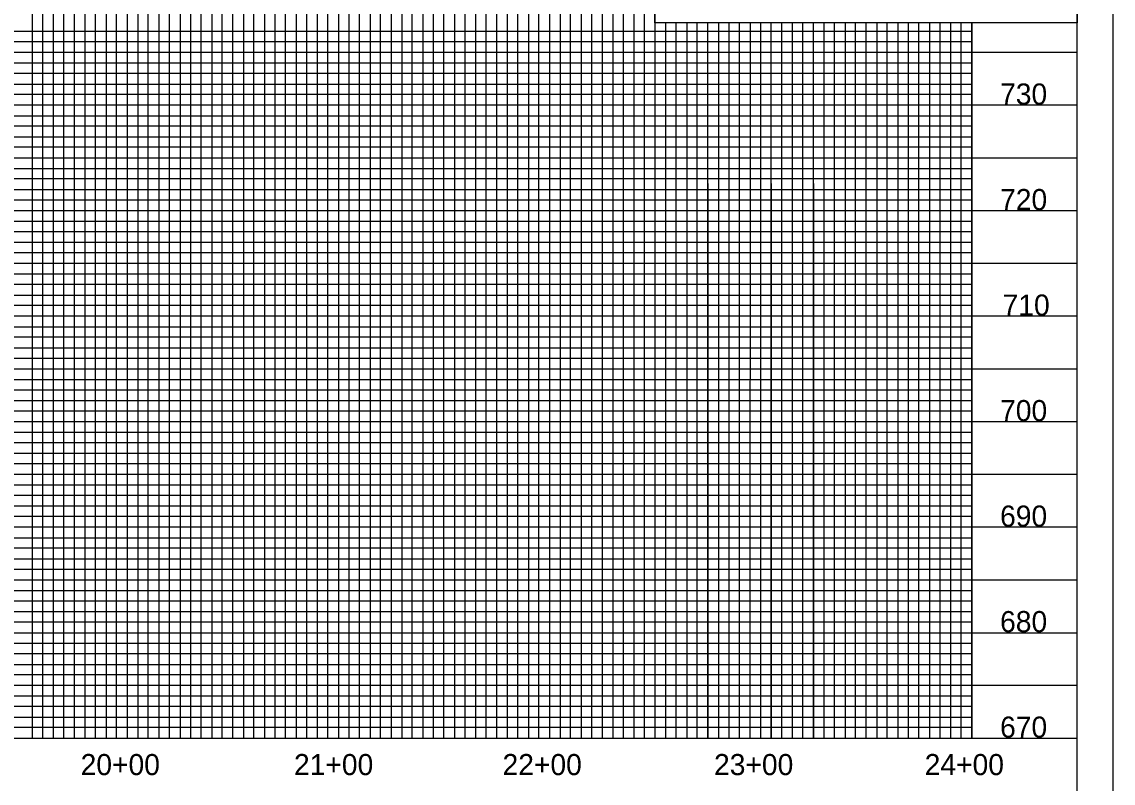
# Model space of a CAD drawing. Extents: x 1524869 to 1526553, y 501099 to 502199.
# Drawn here: x 1526036 to 1526553, y 501652 to 502013 of the extents above; entities that cross this region are included whole.
import ezdxf

# ---------------------------------------------------------------- set-up
doc = ezdxf.new("R2010")
doc.units = 0
for name, color, linetype in [('Exist Vertical Profile Horizontal Axis Label Major', 7, 'Continuous'), ('Exist Vertical Profile Vertical Axis Label', 7, 'Continuous'), ('Sheet Layout Profile Border Port 1', 7, 'Continuous'), ('Sheet Plot Border Outside CELL', 7, 'Continuous'), ('Sheet Profile CELL', 7, 'Continuous'), ('Sheet Profile Grid Major CELL', 7, 'Continuous'), ('Sheet Profile Grid Middle CELL', 7, 'Continuous'), ('Sheet Profile Grid Minor CELL', 7, 'Continuous'), ('Sheet Sticker Exception Certification CELL', 7, 'Continuous')]:
    doc.layers.add(name, color=color, linetype=linetype)

msp = doc.modelspace()

# ---------------------------------------------------------------- linework, layer by layer
at = {"layer": 'Sheet Layout Profile Border Port 1'}
msp.add_lwpolyline([(1525086.08, 502173.56), (1525086.08, 501673.56), (1526486.08, 501673.56), (1526486.08, 502012.51), (1526336.03, 502012.51), (1526336.08, 502173.56)], close=True, dxfattribs=at)
at = {"layer": 'Sheet Plot Border Outside CELL'}
msp.add_lwpolyline([(1524869.08, 501098.56), (1526553.08, 501098.56), (1526553.08, 502198.56), (1524869.08, 502198.56)], close=True, dxfattribs=at)
at = {"layer": 'Sheet Profile CELL'}
msp.add_line((1525036.08, 501673.56), (1526536.08, 501673.56), dxfattribs=at)
msp.add_lwpolyline([(1526536.08, 502173.56), (1525036.08, 502173.56), (1525036.08, 501123.56), (1526536.08, 501123.56)], close=True, dxfattribs=at)
at = {"layer": 'Sheet Profile Grid Major CELL'}
for points in [[(1526036.08, 502173.56), (1526086.08, 502173.56), (1526086.08, 501673.56), (1526136.08, 501673.56), (1526136.08, 502173.56), (1526186.08, 502173.56), (1526186.08, 501673.56), (1526236.08, 501673.56), (1526236.08, 502173.56), (1526286.08, 502173.56), (1526286.08, 501673.56), (1526336.08, 501673.56), (1526336.08, 502173.56), (1526362.38, 502173.56)], [(1526486.08, 502012.51), (1526486.08, 501673.56), (1526536.08, 501673.56), (1526536.08, 502023.56)], [(1526386.08, 502012.51), (1526386.08, 501673.56), (1526436.08, 501673.56), (1526436.08, 501673.56), (1526436.08, 502012.51)], [(1526536.08, 501973.56), (1525036.08, 501973.56), (1525036.08, 501923.56), (1526536.08, 501923.56)], [(1526536.08, 501873.56), (1525036.08, 501873.56), (1525036.08, 501823.56), (1526536.08, 501823.56)], [(1526536.08, 501773.56), (1525036.08, 501773.56), (1525036.08, 501773.56), (1525036.08, 501723.56), (1526536.08, 501723.56)]]:
    msp.add_lwpolyline(points, dxfattribs=at)
at = {"layer": 'Sheet Profile Grid Middle CELL'}
for points in [[(1526011.08, 501673.56), (1526061.08, 501673.56), (1526061.08, 502173.56), (1526111.08, 502173.56), (1526111.08, 501673.56), (1526161.08, 501673.56), (1526161.08, 502173.56), (1526211.08, 502173.56), (1526211.08, 501673.56), (1526261.08, 501673.56), (1526261.08, 502173.56), (1526311.08, 502173.56), (1526311.08, 501673.56), (1526361.08, 501673.56), (1526361.08, 502012.51)], [(1526361.08, 501936.36), (1526361.08, 501673.56), (1526411.08, 501673.56), (1526411.08, 502012.51)], [(1526411.08, 501936.36), (1526411.08, 501673.56), (1526461.08, 501673.56), (1526461.08, 502012.51)], [(1526536.08, 501998.56), (1525036.08, 501998.56), (1525036.08, 501948.56), (1526361.08, 501948.56)], [(1526361.08, 501948.56), (1526536.08, 501948.56)], [(1526536.08, 501898.56), (1525036.08, 501898.56), (1525036.08, 501848.56), (1526536.08, 501848.56)], [(1526536.08, 501798.56), (1525036.08, 501798.56), (1525036.08, 501748.56), (1526536.08, 501748.56)], [(1526536.08, 501698.56), (1525036.08, 501698.56)]]:
    msp.add_lwpolyline(points, dxfattribs=at)
at = {"layer": 'Sheet Profile Grid Minor CELL'}
for p, q in [((1525086.08, 502008.56), (1526486.08, 502008.56)), ((1526486.08, 501988.56), (1525086.08, 501988.56)), ((1525086.08, 501983.56), (1526486.08, 501983.56)), ((1526486.08, 501963.56), (1525086.08, 501963.56)), ((1525086.08, 501958.56), (1526486.08, 501958.56)), ((1526486.08, 501938.56), (1525086.08, 501938.56)), ((1525086.08, 501933.56), (1526486.08, 501933.56)), ((1526486.08, 501928.56), (1525086.08, 501928.56)), ((1525086.08, 501918.56), (1526486.08, 501918.56)), ((1526486.08, 501913.56), (1525086.08, 501913.56)), ((1525086.08, 501908.56), (1526486.08, 501908.56)), ((1526486.08, 501903.56), (1525086.08, 501903.56)), ((1525086.08, 501893.56), (1526486.08, 501893.56)), ((1526486.08, 501888.56), (1525086.08, 501888.56)), ((1525086.08, 501883.56), (1526486.08, 501883.56)), ((1526486.08, 501878.56), (1525086.08, 501878.56)), ((1525086.08, 501868.56), (1526486.08, 501868.56)), ((1526486.08, 501863.56), (1525086.08, 501863.56)), ((1525086.08, 501858.56), (1526486.08, 501858.56)), ((1526486.08, 501853.56), (1525086.08, 501853.56)), ((1525086.08, 501843.56), (1526486.08, 501843.56)), ((1526486.08, 501838.56), (1525086.08, 501838.56)), ((1525086.08, 501833.56), (1526486.08, 501833.56)), ((1526486.08, 501828.56), (1525086.08, 501828.56)), ((1525086.08, 501818.56), (1526486.08, 501818.56)), ((1526486.08, 501813.56), (1525086.08, 501813.56)), ((1525086.08, 501808.56), (1526486.08, 501808.56)), ((1526486.08, 501803.56), (1525086.08, 501803.56)), ((1525086.08, 501793.56), (1526486.08, 501793.56)), ((1526486.08, 501788.56), (1525086.08, 501788.56)), ((1526486.08, 501783.56), (1525086.08, 501783.56)), ((1526486.08, 501778.56), (1525086.08, 501778.56)), ((1525086.08, 501768.56), (1526486.08, 501768.56)), ((1526486.08, 501763.56), (1525086.08, 501763.56)), ((1525086.08, 501758.56), (1526486.08, 501758.56)), ((1526486.08, 501753.56), (1525086.08, 501753.56)), ((1525086.08, 501743.56), (1526486.08, 501743.56)), ((1526486.08, 501738.56), (1525086.08, 501738.56)), ((1525086.08, 501733.56), (1526486.08, 501733.56)), ((1526486.08, 501728.56), (1525086.08, 501728.56)), ((1525086.08, 501718.56), (1526486.08, 501718.56)), ((1526486.08, 501713.56), (1525086.08, 501713.56)), ((1525086.08, 501708.56), (1526486.08, 501708.56)), ((1526486.08, 501703.56), (1525086.08, 501703.56)), ((1525086.08, 501693.56), (1526486.08, 501693.56)), ((1526486.08, 501688.56), (1525086.08, 501688.56)), ((1525086.08, 501683.56), (1526486.08, 501683.56))]:
    msp.add_line(p, q, dxfattribs=at)
for points in [[(1526041.08, 502173.56), (1526041.08, 501673.56), (1526046.08, 501673.56), (1526046.08, 502173.56)], [(1526051.08, 502173.56), (1526051.08, 501673.56), (1526056.08, 501673.56), (1526056.08, 502173.56)], [(1526066.08, 502173.56), (1526066.08, 501673.56), (1526071.08, 501673.56), (1526071.08, 502173.56)], [(1526076.08, 502173.56), (1526076.08, 501673.56), (1526081.08, 501673.56), (1526081.08, 502173.56)], [(1526091.08, 502173.56), (1526091.08, 501673.56), (1526096.08, 501673.56), (1526096.08, 502173.56)], [(1526101.08, 502173.56), (1526101.08, 501673.56), (1526106.08, 501673.56), (1526106.08, 502173.56)], [(1526116.08, 502173.56), (1526116.08, 501673.56), (1526121.08, 501673.56), (1526121.08, 502173.56)], [(1526126.08, 502173.56), (1526126.08, 501673.56), (1526131.08, 501673.56), (1526131.08, 502173.56)], [(1526141.08, 502173.56), (1526141.08, 501673.56), (1526146.08, 501673.56), (1526146.08, 502173.56)], [(1526151.08, 502173.56), (1526151.08, 501673.56), (1526156.08, 501673.56), (1526156.08, 502173.56)], [(1526166.08, 502173.56), (1526166.08, 501673.56), (1526171.08, 501673.56), (1526171.08, 502173.56)], [(1526176.08, 502173.56), (1526176.08, 501673.56), (1526181.08, 501673.56), (1526181.08, 502173.56)], [(1526191.08, 502173.56), (1526191.08, 501673.56), (1526196.08, 501673.56), (1526196.08, 502173.56)], [(1526201.08, 502173.56), (1526201.08, 501673.56), (1526206.08, 501673.56), (1526206.08, 502173.56)], [(1526216.08, 502173.56), (1526216.08, 501673.56), (1526221.08, 501673.56), (1526221.08, 502173.56)], [(1526226.08, 502173.56), (1526226.08, 501673.56)], [(1526226.08, 501673.56), (1526231.08, 501673.56), (1526231.08, 502173.56)], [(1526241.08, 502173.56), (1526241.08, 501673.56), (1526246.08, 501673.56), (1526246.08, 502173.56)], [(1526251.08, 502173.56), (1526251.08, 501673.56), (1526256.08, 501673.56), (1526256.08, 502173.56)], [(1526266.08, 502173.56), (1526266.08, 501673.56), (1526271.08, 501673.56), (1526271.08, 502173.56)], [(1526276.08, 502173.56), (1526276.08, 501673.56), (1526281.08, 501673.56), (1526281.08, 502173.56)], [(1526291.08, 502173.56), (1526291.08, 501673.56), (1526296.08, 501673.56), (1526296.08, 502173.56)], [(1526301.08, 502173.56), (1526301.08, 501673.56), (1526306.08, 501673.56), (1526306.08, 502173.56)], [(1526316.08, 502173.56), (1526316.08, 501673.56), (1526321.08, 501673.56), (1526321.08, 502173.56)], [(1526326.08, 502173.56), (1526326.08, 501673.56), (1526331.08, 501673.56), (1526331.08, 502173.56)], [(1526341.08, 502012.51), (1526341.08, 501673.56), (1526346.08, 501673.56), (1526346.08, 502012.51)], [(1526351.08, 502012.51), (1526351.08, 501673.56), (1526356.08, 501673.56), (1526356.08, 502012.51)], [(1526366.08, 502012.51), (1526366.08, 501673.56), (1526366.08, 501673.56), (1526371.08, 501673.56), (1526376.08, 501673.56), (1526376.08, 502012.51)], [(1526371.08, 502012.51), (1526371.08, 501673.56)], [(1526381.07, 502012.51), (1526380.98, 501673.61), (1526385.98, 501673.61), (1526391.08, 501673.56), (1526391.08, 502012.51)], [(1526391.08, 501936.36), (1526391.08, 501673.56), (1526396.08, 501673.56), (1526396.08, 502012.51)], [(1526401.08, 502012.51), (1526401.08, 501673.56), (1526406.08, 501673.56), (1526406.08, 502012.51)], [(1526416.08, 502012.51), (1526416.08, 501673.56), (1526421.08, 501673.56), (1526421.08, 502012.51)], [(1526426.08, 502012.51), (1526426.08, 501673.56), (1526431.08, 501673.56), (1526431.08, 502012.51)], [(1526441.08, 502012.51), (1526441.08, 501673.56), (1526446.08, 501673.56), (1526446.08, 502012.51)], [(1526451.08, 502012.51), (1526451.08, 501673.56), (1526456.08, 501673.56), (1526456.08, 502012.51)], [(1526466.08, 502012.51), (1526466.08, 501673.56), (1526471.08, 501673.56), (1526471.08, 502012.51)], [(1526476.08, 502012.51), (1526476.08, 501673.56), (1526481.08, 501673.56), (1526481.08, 502012.51)], [(1526486.08, 502003.56), (1525086.08, 502003.56), (1525086.08, 501993.56), (1526486.08, 501993.56)], [(1526486.08, 501978.56), (1525086.08, 501978.56), (1525086.08, 501968.56), (1526486.08, 501968.56)], [(1526486.08, 501953.56), (1525086.08, 501953.56), (1525086.08, 501943.56), (1526486.08, 501943.56)], [(1526486.08, 501678.56), (1525086.08, 501678.56)]]:
    msp.add_lwpolyline(points, dxfattribs=at)
at = {"layer": 'Sheet Sticker Exception Certification CELL'}
for p, q in [((1526336.03, 502012.51), (1526336.03, 502036.01)), ((1526336.03, 502012.51), (1526336.03, 502036.01)), ((1526536.07, 502036), (1526536.07, 502012.5)), ((1526536.07, 502036), (1526536.07, 502012.5)), ((1526536.07, 502012.51), (1526336.03, 502012.51)), ((1526536.07, 502012.51), (1526336.03, 502012.51))]:
    msp.add_line(p, q, dxfattribs=at)

# ---------------------------------------------------------------- texts
at = {"layer": 'Exist Vertical Profile Horizontal Axis Label Major'}
for s, p in [('20+00', (1526064.01, 501656.06)), ('21+00', (1526165.07, 501656.06)), ('22+00', (1526263.85, 501656.06)), ('23+00', (1526364.02, 501656.06)), ('24+00', (1526463.8, 501656.06))]:
    msp.add_text(s, height=10, dxfattribs=at).set_placement(p)
at = {"layer": 'Exist Vertical Profile Vertical Axis Label'}
for s, p in [('730', (1526499.51, 501973.81)), ('720', (1526499.51, 501923.81)), ('710', (1526500.71, 501873.81)), ('700', (1526499.51, 501823.81)), ('690', (1526499.51, 501773.81)), ('680', (1526499.51, 501723.81)), ('670', (1526499.51, 501673.81))]:
    msp.add_text(s, height=10, dxfattribs=at).set_placement(p)

doc.saveas('drawing.dxf')
